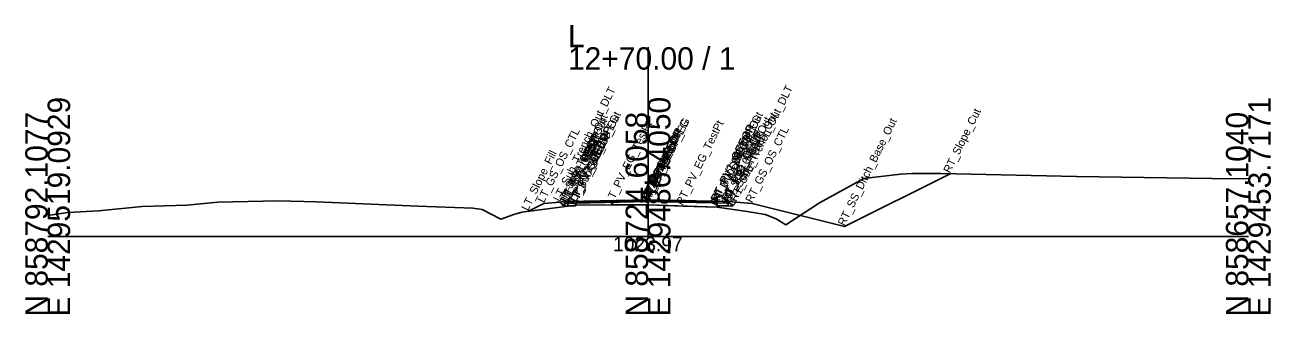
# Model space of a CAD drawing. Extents: x -26 to 2303, y -10 to 19558.
# Drawn here: x 1147.2 to 1302.8, y 3990.3 to 4026.5 of the extents above; entities that cross this region are included whole.
import ezdxf

# ---------------------------------------------------------------- set-up
doc = ezdxf.new("R2010")
doc.units = 0
for name, color, linetype in [('Default', 7, 'Continuous'), ('Exist CMT Pavement', 7, 'Continuous'), ('Exist Cross Section Cell', 7, 'Continuous'), ('Exist XS Center Line Elevation Label', 7, 'Continuous'), ('Exist XS Ground Line', 7, 'Continuous'), ('Prop CMT Conc Surface', 7, 'Continuous'), ('Prop CMT Pvmt Course 1', 7, 'Continuous'), ('Prop CMT Pvmt Course 1 Wedge', 7, 'Continuous'), ('Prop CMT Pvmt Course 2', 7, 'Continuous'), ('Prop CMT Pvmt Course 2 Wedge', 7, 'Continuous'), ('Prop CMT Pvmt Surface', 7, 'Continuous'), ('Prop CMT Pvmt Surface Shoulder', 7, 'Continuous'), ('Prop CMT Pvmt Wedge Surface 1', 7, 'Continuous'), ('Prop CMT Pvmt Wedge Surface 2', 7, 'Continuous'), ('Prop CMT Shld Paved Course 1', 7, 'Continuous'), ('Prop CMT Shld Paved Course 2', 7, 'Continuous'), ('Prop CMT Slope Grass', 7, 'Continuous'), ('Prop CMT Subgrade Earthwork', 7, 'Continuous'), ('Prop XS Dump Level', 7, 'Continuous')]:
    doc.layers.add(name, color=color, linetype=linetype)

msp = doc.modelspace()

# ---------------------------------------------------------------- linework, layer by layer
at = {"layer": 'Exist CMT Pavement'}
for p, q in [((1220.72, 4004.29), (1215.99, 4004.2)), ((1215.99, 4004.2), (1215.99, 4003.94)), ((1220.39, 4003.96), (1220.72, 4004.29)), ((1215.99, 4003.94), (1216, 4003.94)), ((1216, 4003.94), (1220.39, 4003.96)), ((1216, 4003.94), (1216, 4003.94))]:
    msp.add_line(p, q, dxfattribs=at)
for points in [[(1225, 4003.97), (1215.99, 4003.94)], [(1215.99, 4003.94), (1220.49, 4003.96)], [(1216, 4003.94), (1216, 4003.94)], [(1220.49, 4003.96), (1225, 4003.97)], [(1229.33, 4003.83), (1225, 4003.97)], [(1225, 4003.97), (1233.66, 4003.7)], [(1233.66, 4003.7), (1229.33, 4003.83)]]:
    msp.add_lwpolyline(points, dxfattribs=at)
at = {"layer": 'Exist Cross Section Cell'}
for p, q in [((1225, 4000), (1225, 4023.69)), ((1150, 4000), (1225, 4000)), ((1225, 4000), (1300, 4000))]:
    msp.add_line(p, q, dxfattribs=at)
at = {"layer": 'Exist XS Ground Line'}
msp.add_lwpolyline([(1150, 4002.65), (1152.52, 4003.03), (1156.33, 4003.23), (1161.82, 4003.78), (1167.37, 4003.93), (1171.24, 4004.3), (1178.79, 4004.47), (1183.59, 4004.37), (1196.26, 4003.81), (1203.1, 4003.58), (1204.27, 4003.38), (1206.63, 4002.2), (1208.22, 4002.78), (1209.25, 4003.05), (1215.64, 4003.9), (1215.99, 4003.94), (1224.68, 4003.98), (1225, 4003.97), (1228.38, 4003.86), (1233.66, 4003.7), (1237.38, 4003.14), (1239.64, 4002.77), (1241.02, 4002.23), (1242.2, 4001.49), (1246.41, 4004.21), (1251.96, 4007.28), (1256.54, 4007.8), (1258.01, 4007.9), (1261.6, 4007.88), (1278.54, 4007.51), (1295.44, 4007.28), (1300, 4007.25)], dxfattribs=at)
at = {"layer": 'Prop CMT Conc Surface'}
msp.add_line((1233.66, 4003.7), (1233.66, 4003.87), dxfattribs=at)
at = {"layer": 'Prop CMT Pvmt Course 1'}
for points in [[(1225, 4004.59), (1215, 4004.39)], [(1215, 4004.39), (1215, 4004.18)], [(1215, 4004.18), (1215.99, 4004.2)], [(1215.99, 4004.28), (1225, 4004.46)], [(1215.99, 4004.2), (1215.99, 4004.28)], [(1225, 4004.38), (1225, 4004.59)], [(1225, 4004.59), (1235, 4004.39)], [(1225, 4004.38), (1225, 4004.59)], [(1225, 4004.46), (1225, 4004.38), (1225, 4004.38)], [(1233.66, 4004.29), (1225, 4004.46)], [(1225, 4004.46), (1225, 4004.38), (1225, 4004.38)], [(1233.66, 4004.21), (1233.66, 4004.29)], [(1235, 4004.18), (1233.66, 4004.21)], [(1235, 4004.39), (1235, 4004.18)]]:
    msp.add_lwpolyline(points, dxfattribs=at)
at = {"layer": 'Prop CMT Pvmt Course 1 Wedge'}
for points in [[(1225, 4004.46), (1215.99, 4004.28)], [(1225, 4004.46), (1233.66, 4004.29)]]:
    msp.add_lwpolyline(points, dxfattribs=at)
at = {"layer": 'Prop CMT Pvmt Course 2'}
for points in [[(1215.99, 4004.2), (1215, 4004.18)], [(1215, 4004.18), (1215, 4003.85)], [(1215.99, 4003.86), (1215.99, 4004.2)], [(1233.66, 4003.87), (1233.66, 4005.05)], [(1233.66, 4004.21), (1235, 4004.18)], [(1235, 4004.18), (1235, 4003.85)], [(1215, 4003.85), (1215.99, 4003.86)], [(1235, 4003.85), (1233.66, 4003.87)]]:
    msp.add_lwpolyline(points, dxfattribs=at)
at = {"layer": 'Prop CMT Pvmt Course 2 Wedge'}
for points in [[(1225, 4004.38), (1215.99, 4004.2)], [(1225, 4004.38), (1233.66, 4004.21)]]:
    msp.add_lwpolyline(points, dxfattribs=at)
at = {"layer": 'Prop CMT Pvmt Surface'}
for points in [[(1225, 4004.59), (1215, 4004.39)], [(1225, 4004.59), (1235, 4004.39)]]:
    msp.add_lwpolyline(points, dxfattribs=at)
at = {"layer": 'Prop CMT Pvmt Surface Shoulder'}
for points in [[(1215, 4004.39), (1215, 4004.39)], [(1235, 4004.39), (1235, 4004.39)]]:
    msp.add_lwpolyline(points, dxfattribs=at)
at = {"layer": 'Prop CMT Pvmt Wedge Surface 1'}
for points in [[(1215, 4004.18), (1215, 4004.39)], [(1215.99, 4004.2), (1215, 4004.18)], [(1225, 4004.46), (1215.99, 4004.28)], [(1215.99, 4004.28), (1215.99, 4004.2)], [(1225, 4004.46), (1233.66, 4004.29)], [(1233.66, 4004.29), (1233.66, 4004.21)], [(1233.66, 4004.21), (1235, 4004.18)], [(1235, 4004.18), (1235, 4004.39)]]:
    msp.add_lwpolyline(points, dxfattribs=at)
at = {"layer": 'Prop CMT Pvmt Wedge Surface 2'}
for points in [[(1215, 4004.18), (1215, 4004.39)], [(1225, 4004.38), (1215, 4004.18)], [(1225, 4004.38), (1235, 4004.18)], [(1235, 4004.18), (1235, 4004.39)]]:
    msp.add_lwpolyline(points, dxfattribs=at)
at = {"layer": 'Prop CMT Shld Paved Course 1'}
for points in [[(1215, 4004.39), (1214.79, 4004.17)], [(1214.79, 4004.17), (1215, 4004.18)], [(1215, 4004.39), (1215, 4004.39)], [(1215, 4004.18), (1215, 4004.39)], [(1235, 4004.39), (1235, 4004.39)], [(1235, 4004.39), (1235.21, 4004.17)], [(1235, 4004.18), (1235, 4004.39)], [(1235.21, 4004.17), (1235, 4004.18)]]:
    msp.add_lwpolyline(points, dxfattribs=at)
at = {"layer": 'Prop CMT Shld Paved Course 2'}
for points in [[(1214.79, 4004.17), (1214.45, 4003.83)], [(1215, 4004.18), (1214.79, 4004.17)], [(1214.79, 4004.17), (1214.79, 4004.17)], [(1215, 4003.85), (1215, 4004.18)], [(1220.72, 4004.29), (1220.38, 4003.96)], [(1235, 4004.18), (1235.21, 4004.17)], [(1235, 4003.85), (1235, 4004.18)], [(1235.21, 4004.17), (1235.21, 4004.17)], [(1235.21, 4004.17), (1235.55, 4003.83)], [(1214.45, 4003.83), (1215, 4003.85)], [(1235.55, 4003.83), (1235, 4003.85)]]:
    msp.add_lwpolyline(points, dxfattribs=at)
at = {"layer": 'Prop CMT Slope Grass'}
for points in [[(1235, 4004.39), (1238, 4004.15), (1249.54, 4001.26), (1262.73, 4007.86)], [(1215, 4004.39), (1212, 4004.15), (1210, 4003.15)]]:
    msp.add_lwpolyline(points, dxfattribs=at)
at = {"layer": 'Prop CMT Subgrade Earthwork'}
for points in [[(1214.45, 4003.83), (1213.98, 4004.3)], [(1235.55, 4003.83), (1236.02, 4004.3)], [(1215, 4003.85), (1214.45, 4003.83)], [(1215.99, 4003.86), (1215, 4003.85)], [(1215.99, 4003.86), (1216, 4003.94)], [(1233.66, 4003.87), (1233.65, 4003.7)], [(1233.66, 4003.87), (1235, 4003.85)], [(1235, 4003.85), (1235.55, 4003.83)]]:
    msp.add_lwpolyline(points, dxfattribs=at)

# ---------------------------------------------------------------- texts
at = {"layer": 'Default'}
msp.add_text('-', height=0.0001, dxfattribs=at).set_placement((1150, 4000))
at = {"layer": 'Exist Cross Section Cell'}
for s, p in [('L', (1215, 4023.69)), ('12+70.00 / 1', (1215, 4020.89))]:
    msp.add_text(s, height=2.8, dxfattribs=at).set_placement(p)
for s, p in [('E 1429519.0929', (1152.8, 3990)), ('E 1429486.4050', (1227.8, 3990)), ('E 1429453.7171', (1302.8, 3990)), ('N 858792.1077', (1150, 3990)), ('N 858724.6058', (1225, 3990)), ('N 858657.1040', (1300, 3990))]:
    msp.add_text(s, height=2.8, rotation=90, dxfattribs=at).set_placement(p)
at = {"layer": 'Exist XS Center Line Elevation Label'}
msp.add_text('1023.97', height=1.8, dxfattribs=at).set_placement((1220.63, 3998.17))
at = {"layer": 'Prop XS Dump Level'}
for s, p in [('LT_Sub_Trench_Out_DLT', (1213.98, 4004.3)), ('RT_Sub_Trench_Out_DLT', (1236.02, 4004.3)), ('LT_Sub_Trench_Out', (1214.45, 4003.83)), ('LT_PV_OEEOP_EG', (1215.99, 4003.94)), ('LT_PV_Sub_Tie_Out', (1216, 4003.94)), ('RT_PV_Sub_Tie_Out', (1233.65, 4003.7)), ('RT_PV_OEEOP_EG', (1233.66, 4003.7)), ('RT_Sub_Trench_Out', (1235.55, 4003.83)), ('RT_Slope_Cut', (1262.73, 4007.86)), ('LT_PS2_Shelf_Out', (1214.79, 4004.17)), ('LT_PV1_OEEOP', (1215.99, 4004.28)), ('LT_PV2_OEEOP', (1215.99, 4004.2)), ('LT_PV_EG_TestPt', (1220.49, 4003.96)), ('RT_PV_IEEOP_EG', (1225, 4003.97)), ('LT_PV_IEEOP_EG', (1225, 4003.97)), ('RT_PV1_IEEOP', (1225, 4004.46)), ('RT_PV2_IEEOP', (1225, 4004.38)), ('RT_PV_EG_TestPt', (1229.33, 4003.83)), ('RT_PV1_OEEOP', (1233.66, 4004.29)), ('RT_PV2_OEEOP', (1233.66, 4004.21)), ('RT_Sub_OEEOP', (1233.66, 4003.87)), ('RT_PS2_Shelf_Out', (1235.21, 4004.17)), ('RT_GS_OS_CTL', (1238, 4004.15)), ('RT_SS_Ditch_Base_Out', (1249.54, 4001.26)), ('LT_GS_OS_CTL', (1212, 4004.15)), ('LT_PS2_OEOP', (1214.79, 4004.17)), ('LT_PV1_OEOT', (1215, 4004.39)), ('LT_PS1_OEOP', (1215, 4004.39)), ('LT_PV2_OEOT', (1215, 4004.18)), ('LT_Sub_OEOT', (1215, 4003.85)), ('LT_Sub_OEEOP', (1215.99, 4003.86)), ('LT_PV1_IEEOP', (1225, 4004.46)), ('LT_PV2_IEEOP', (1225, 4004.38)), ('RT_PV1_OEOT', (1235, 4004.39)), ('RT_PS1_OEOP', (1235, 4004.39)), ('RT_PV2_OEOT', (1235, 4004.18)), ('RT_Sub_OEOT', (1235, 4003.85)), ('RT_PS2_OEOP', (1235.21, 4004.17)), ('LT_Slope_Fill', (1210, 4003.15)), ('PV1_PGL', (1225, 4004.59)), ('PV2_PGL', (1225, 4004.38))]:
    msp.add_text(s, height=1, rotation=63.5833, dxfattribs=at).set_placement(p)

doc.saveas('drawing.dxf')
